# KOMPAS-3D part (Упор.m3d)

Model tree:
1. Эскиз:1
2. Операция выдавливания:1
     Расстояние 1 = 30; Расстояние 2 = 3
3. Эскиз:2
4. Операция выдавливания:2
     Расстояние 1 = 6; Расстояние 2 = 3
5. Эскиз:3
6. Операция выдавливания:3
     Расстояние 1 = 12; Расстояние 2 = 3
7. Фаска:1
     Угол = 45; Длина 1 = 1; Длина 2 = 1
8. Фаска:2
     Угол = 45; Длина 1 = 1; Длина 2 = 1
9. Эскиз:4
10. Вырезать элемент выдавливания:1
     Расстояние 2 = 40; Расстояние 1 = 8.88395
